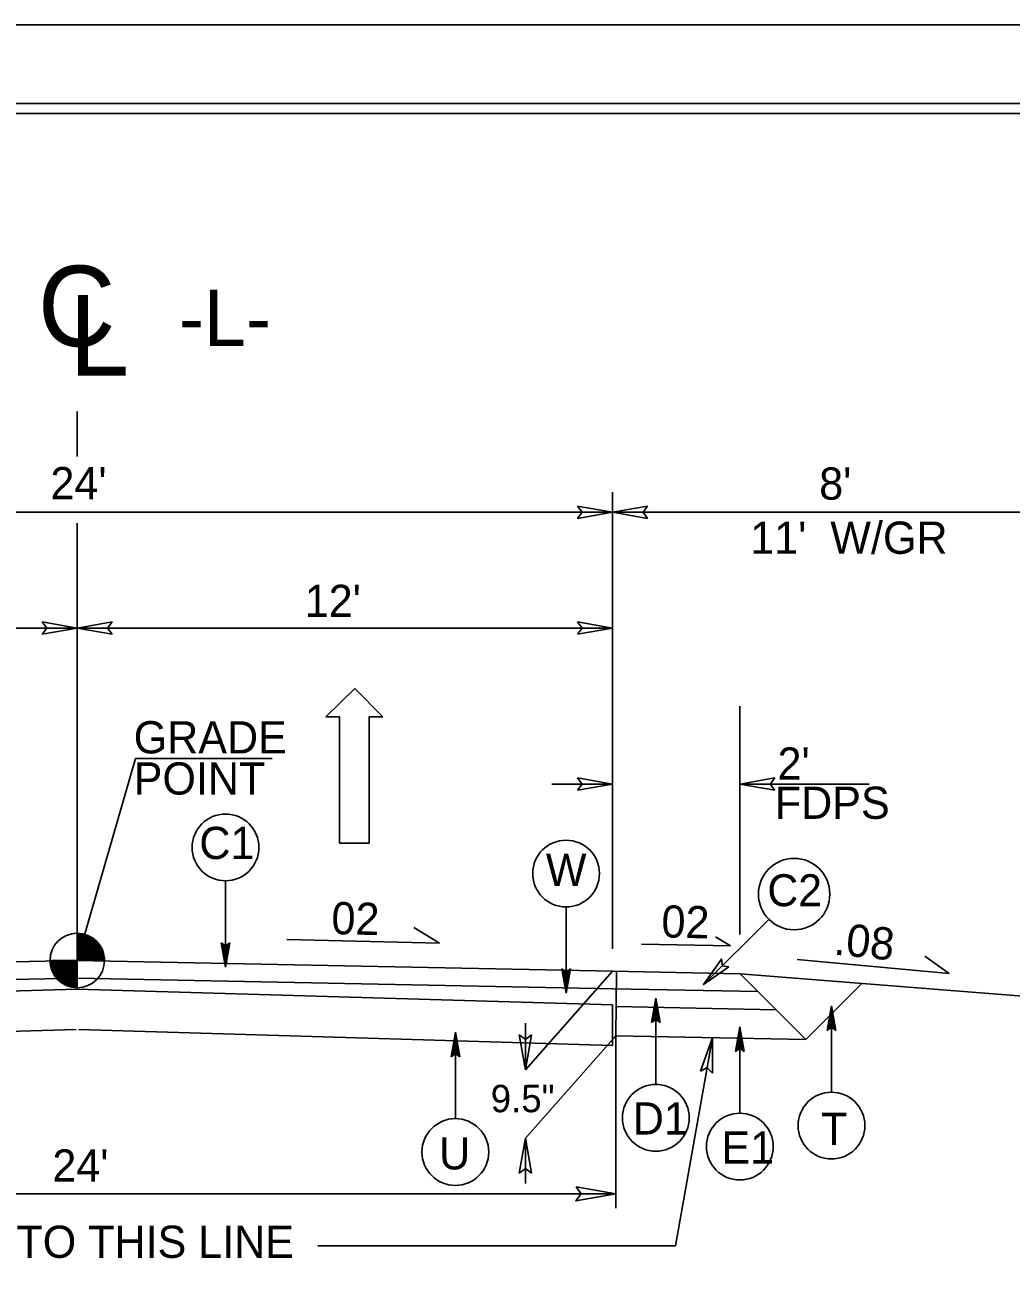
# Model space of a CAD drawing. Extents: x 2532463 to 2534146, y 189689 to 190784.
# Drawn here: x 2533450.3 to 2533701.3, y 190466.5 to 190784.2 of the extents above; entities that cross this region are included whole.
import ezdxf

# ---------------------------------------------------------------- set-up
doc = ezdxf.new("R2010")
doc.units = 0
for name, color, linetype in [('Old_Level_1', 7, 'Continuous'), ('Old_Level_11', 7, 'Continuous'), ('Old_Level_12', 7, 'Continuous'), ('Old_Level_18', 7, 'Continuous'), ('Old_Level_2', 7, 'Continuous'), ('Old_Level_3', 7, 'Continuous'), ('Old_Level_4', 7, 'Continuous'), ('Old_Level_50', 7, 'Continuous'), ('Old_Level_51', 7, 'Continuous'), ('Typical Bridge Rail CELL', 7, 'Continuous'), ('Typical Curb CELL', 7, 'Continuous'), ('Typical ID Circle CELL', 7, 'Continuous'), ('Typical Shoulder Slope Information CELL', 7, 'Continuous')]:
    doc.layers.add(name, color=color, linetype=linetype)

msp = doc.modelspace()

# ---------------------------------------------------------------- linework, layer by layer
at = {"layer": 'Old_Level_1'}
for p, q in [((2533463.59, 190552.98), (2533463.59, 190546.03)), ((2533463.59, 190546.03), (2533463.59, 190552.98)), ((2533501.34, 190544.33), (2533500.24, 190550.56)), ((2533501.34, 190549.75), (2533500.24, 190550.56)), ((2533501.34, 190544.33), (2533500.4, 190550.45)), ((2533500.55, 190550.33), (2533501.34, 190544.33)), ((2533501.34, 190544.33), (2533500.71, 190550.21)), ((2533501.34, 190544.33), (2533502.44, 190550.56)), ((2533502.44, 190550.56), (2533501.34, 190549.75)), ((2533502.28, 190550.45), (2533501.34, 190544.33)), ((2533501.34, 190544.33), (2533502.12, 190550.33)), ((2533501.97, 190550.21), (2533501.34, 190544.33)), ((2533500.87, 190550.1), (2533501.34, 190544.33)), ((2533501.34, 190544.33), (2533501.02, 190549.99)), ((2533501.18, 190549.87), (2533501.34, 190544.33)), ((2533501.34, 190544.33), (2533501.81, 190550.1)), ((2533501.66, 190549.99), (2533501.34, 190544.33)), ((2533501.34, 190544.33), (2533501.5, 190549.87)), ((2533501.34, 190549.75), (2533501.34, 190544.33)), ((2533463.59, 190546.03), (2533327.27, 190543.31)), ((2533456.64, 190546.03), (2533463.59, 190546.03)), ((2533463.59, 190546.03), (2533463.59, 190539.09)), ((2533470.53, 190546.03), (2533463.59, 190546.03)), ((2533463.59, 190546.03), (2533599.9, 190543.31)), ((2533588.05, 190537.67), (2533586.96, 190543.9)), ((2533588.05, 190543.09), (2533586.96, 190543.9)), ((2533588.05, 190537.67), (2533587.11, 190543.79)), ((2533588.05, 190537.67), (2533589.15, 190543.9)), ((2533589.15, 190543.9), (2533588.05, 190543.09)), ((2533589, 190543.79), (2533588.05, 190537.67)), ((2533463.59, 190541.52), (2533327.27, 190538.8)), ((2533463.59, 190541.52), (2533599.9, 190538.8)), ((2533587.27, 190543.67), (2533588.05, 190537.67)), ((2533588.05, 190537.67), (2533587.43, 190543.55)), ((2533587.58, 190543.44), (2533588.05, 190537.67)), ((2533588.05, 190537.67), (2533587.74, 190543.33)), ((2533587.9, 190543.21), (2533588.05, 190537.67)), ((2533588.05, 190537.67), (2533588.84, 190543.67)), ((2533588.68, 190543.55), (2533588.05, 190537.67)), ((2533588.05, 190537.67), (2533588.53, 190543.44)), ((2533588.37, 190543.33), (2533588.05, 190537.67)), ((2533588.05, 190537.67), (2533588.21, 190543.21)), ((2533588.05, 190543.09), (2533588.05, 190537.67)), ((2533599.9, 190543.31), (2533632.37, 190542.66)), ((2533600.85, 190543.29), (2533600.75, 190526.87)), ((2533632.37, 190542.66), (2533649.13, 190525.9)), ((2533632.37, 190542.66), (2533710.89, 190536.38)), ((2533463.67, 190538.69), (2533327.27, 190534.75)), ((2533463.51, 190538.69), (2533599.9, 190534.75)), ((2533599.9, 190538.83), (2533636.94, 190538.09)), ((2533663.4, 190540.18), (2533649.13, 190525.9)), ((2533599.9, 190534.75), (2533599.9, 190524.39)), ((2533600.75, 190534.3), (2533641.54, 190533.49)), ((2533610.9, 190536.44), (2533609.8, 190530.21)), ((2533609.96, 190530.32), (2533610.9, 190536.44)), ((2533610.9, 190536.44), (2533610.12, 190530.44)), ((2533610.28, 190530.56), (2533610.9, 190536.44)), ((2533610.9, 190536.44), (2533610.43, 190530.67)), ((2533610.59, 190530.78), (2533610.9, 190536.44)), ((2533610.9, 190536.44), (2533610.75, 190530.9)), ((2533610.9, 190536.44), (2533612, 190530.21)), ((2533610.9, 190531.02), (2533610.9, 190536.44)), ((2533611.06, 190530.9), (2533610.9, 190536.44)), ((2533610.9, 190536.44), (2533611.22, 190530.78)), ((2533611.37, 190530.67), (2533610.9, 190536.44)), ((2533610.9, 190536.44), (2533611.53, 190530.56)), ((2533611.69, 190530.44), (2533610.9, 190536.44)), ((2533610.9, 190536.44), (2533611.85, 190530.32)), ((2533655.64, 190534.47), (2533654.54, 190528.24)), ((2533654.7, 190528.36), (2533655.64, 190534.47)), ((2533655.64, 190534.47), (2533654.85, 190528.47)), ((2533655.01, 190528.59), (2533655.64, 190534.47)), ((2533655.64, 190534.47), (2533655.17, 190528.7)), ((2533655.32, 190528.81), (2533655.64, 190534.47)), ((2533655.64, 190534.47), (2533655.48, 190528.93)), ((2533655.64, 190534.47), (2533656.74, 190528.24)), ((2533655.64, 190529.05), (2533655.64, 190534.47)), ((2533655.8, 190528.93), (2533655.64, 190534.47)), ((2533655.64, 190534.47), (2533655.95, 190528.81)), ((2533656.11, 190528.7), (2533655.64, 190534.47)), ((2533655.64, 190534.47), (2533656.27, 190528.59)), ((2533656.42, 190528.47), (2533655.64, 190534.47)), ((2533655.64, 190534.47), (2533656.58, 190528.36)), ((2533463.28, 190528.44), (2533327.27, 190524.39)), ((2533463.9, 190528.44), (2533599.9, 190524.39)), ((2533609.8, 190530.21), (2533610.9, 190531.02)), ((2533610.9, 190531.02), (2533612, 190530.21)), ((2533632.29, 190529.13), (2533631.19, 190522.89)), ((2533631.34, 190523.01), (2533632.29, 190529.13)), ((2533632.29, 190529.13), (2533631.5, 190523.13)), ((2533631.66, 190523.24), (2533632.29, 190529.13)), ((2533632.29, 190529.13), (2533631.82, 190523.36)), ((2533631.97, 190523.47), (2533632.29, 190529.13)), ((2533632.29, 190529.13), (2533632.13, 190523.59)), ((2533632.29, 190529.13), (2533633.39, 190522.89)), ((2533632.29, 190523.7), (2533632.29, 190529.13)), ((2533632.44, 190523.59), (2533632.29, 190529.13)), ((2533632.29, 190529.13), (2533632.6, 190523.47)), ((2533632.76, 190523.36), (2533632.29, 190529.13)), ((2533632.29, 190529.13), (2533632.91, 190523.24)), ((2533633.07, 190523.13), (2533632.29, 190529.13)), ((2533632.29, 190529.13), (2533633.23, 190523.01)), ((2533654.54, 190528.24), (2533655.64, 190529.05)), ((2533655.64, 190529.05), (2533656.74, 190528.24)), ((2533559.86, 190527.74), (2533558.76, 190521.5)), ((2533558.92, 190521.62), (2533559.86, 190527.74)), ((2533559.86, 190527.74), (2533559.08, 190521.74)), ((2533559.24, 190521.85), (2533559.86, 190527.74)), ((2533559.86, 190527.74), (2533559.39, 190521.97)), ((2533559.55, 190522.08), (2533559.86, 190527.74)), ((2533559.86, 190527.74), (2533559.71, 190522.2)), ((2533559.86, 190527.74), (2533560.96, 190521.5)), ((2533559.86, 190522.31), (2533559.86, 190527.74)), ((2533560.02, 190522.2), (2533559.86, 190527.74)), ((2533559.86, 190527.74), (2533560.18, 190522.08)), ((2533560.33, 190521.97), (2533559.86, 190527.74)), ((2533559.86, 190527.74), (2533560.49, 190521.85)), ((2533560.65, 190521.74), (2533559.86, 190527.74)), ((2533559.86, 190527.74), (2533560.81, 190521.62)), ((2533600.75, 190526.87), (2533649.13, 190525.9)), ((2533558.76, 190521.5), (2533559.86, 190522.31)), ((2533559.86, 190522.31), (2533560.96, 190521.5)), ((2533631.19, 190522.89), (2533632.29, 190523.7)), ((2533632.29, 190523.7), (2533633.39, 190522.89))]:
    msp.add_line(p, q, dxfattribs=at)
for points in [[(2533463.69, 190546.03), (2533463.69, 190552.98), (2533463.69, 190552.98)], [(2533463.82, 190546.03), (2533463.82, 190552.97)], [(2533463.96, 190546.03), (2533463.96, 190552.96)], [(2533464.1, 190546.03), (2533464.1, 190552.96)], [(2533464.24, 190546.03), (2533464.24, 190552.95)], [(2533464.38, 190546.03), (2533464.38, 190552.93)], [(2533464.52, 190546.03), (2533464.52, 190552.92)], [(2533464.66, 190546.03), (2533464.66, 190552.89)], [(2533464.79, 190546.03), (2533464.8, 190552.87)], [(2533464.93, 190546.03), (2533464.94, 190552.85)], [(2533465.07, 190546.03), (2533465.07, 190552.82)], [(2533465.21, 190546.03), (2533465.21, 190552.78)], [(2533465.35, 190546.03), (2533465.35, 190552.75)], [(2533465.49, 190546.03), (2533465.49, 190552.71)], [(2533465.63, 190546.03), (2533465.63, 190552.67)], [(2533465.77, 190546.03), (2533465.77, 190552.63)], [(2533465.9, 190546.03), (2533465.9, 190552.58)], [(2533466.05, 190546.03), (2533466.05, 190552.53)], [(2533466.18, 190546.03), (2533466.19, 190552.47)], [(2533466.32, 190546.03), (2533466.32, 190552.42)], [(2533466.46, 190546.03), (2533466.47, 190552.35)], [(2533466.6, 190546.03), (2533466.6, 190552.29)], [(2533466.74, 190546.03), (2533466.74, 190552.22)], [(2533466.88, 190546.03), (2533466.88, 190552.15)], [(2533467.02, 190546.03), (2533467.02, 190552.07)], [(2533467.15, 190546.03), (2533467.16, 190551.99)], [(2533467.3, 190546.03), (2533467.3, 190551.9)], [(2533467.43, 190546.03), (2533467.44, 190551.81)], [(2533467.57, 190546.03), (2533467.57, 190551.72)], [(2533467.71, 190546.03), (2533467.71, 190551.62)], [(2533467.85, 190546.03), (2533467.85, 190551.51)], [(2533467.99, 190546.03), (2533467.99, 190551.4)], [(2533468.13, 190546.03), (2533468.13, 190551.28)], [(2533468.27, 190546.03), (2533468.27, 190551.16)], [(2533468.4, 190546.03), (2533468.41, 190551.03)], [(2533468.55, 190546.03), (2533468.55, 190550.89)], [(2533468.68, 190546.03), (2533468.68, 190550.75)], [(2533468.82, 190546.03), (2533468.82, 190550.59)], [(2533468.96, 190546.03), (2533468.96, 190550.43)], [(2533469.1, 190546.03), (2533469.1, 190550.25)], [(2533469.24, 190546.03), (2533469.24, 190550.07)], [(2533469.38, 190546.03), (2533469.38, 190549.86)], [(2533469.52, 190546.03), (2533469.52, 190549.64)], [(2533469.66, 190546.03), (2533469.65, 190549.41)], [(2533469.8, 190546.03), (2533469.8, 190549.15)], [(2533469.93, 190546.03), (2533469.93, 190548.85)], [(2533470.07, 190546.03), (2533470.07, 190548.51)], [(2533470.21, 190546.03), (2533470.21, 190548.11)], [(2533470.35, 190546.03), (2533470.35, 190547.61)], [(2533456.72, 190545.05), (2533456.72, 190546.03)], [(2533456.85, 190544.35), (2533456.85, 190546.04)], [(2533456.99, 190543.86), (2533456.99, 190546.04)], [(2533457.13, 190543.48), (2533457.13, 190546.03)], [(2533457.27, 190543.16), (2533457.27, 190546.04)], [(2533457.41, 190542.86), (2533457.41, 190546.04)], [(2533457.55, 190542.61), (2533457.55, 190546.03)], [(2533457.69, 190542.38), (2533457.69, 190546.04)], [(2533457.82, 190542.16), (2533457.82, 190546.04)], [(2533457.96, 190541.96), (2533457.97, 190546.03)], [(2533458.1, 190541.78), (2533458.1, 190546.04)], [(2533458.24, 190541.61), (2533458.24, 190546.04)], [(2533458.38, 190541.44), (2533458.38, 190546.03)], [(2533458.52, 190541.29), (2533458.52, 190546.04)], [(2533458.66, 190541.15), (2533458.66, 190546.04)], [(2533458.8, 190541.01), (2533458.8, 190546.03)], [(2533458.93, 190540.88), (2533458.94, 190546.04)], [(2533459.07, 190540.76), (2533459.07, 190546.03)], [(2533459.21, 190540.64), (2533459.22, 190546.03)], [(2533459.35, 190540.53), (2533459.35, 190546.03)], [(2533459.49, 190540.43), (2533459.49, 190546.03)], [(2533459.63, 190540.33), (2533459.63, 190546.03)], [(2533459.77, 190540.24), (2533459.77, 190546.03)], [(2533459.9, 190540.14), (2533459.91, 190546.03)], [(2533460.05, 190540.06), (2533460.05, 190546.03)], [(2533460.18, 190539.98), (2533460.19, 190546.03)], [(2533460.33, 190539.91), (2533460.33, 190546.03)], [(2533460.46, 190539.83), (2533460.46, 190546.03)], [(2533460.6, 190539.76), (2533460.6, 190546.03)], [(2533460.74, 190539.7), (2533460.74, 190546.03)], [(2533460.88, 190539.64), (2533460.88, 190546.03)], [(2533461.02, 190539.58), (2533461.02, 190546.03)], [(2533461.16, 190539.53), (2533461.16, 190546.03)], [(2533461.29, 190539.48), (2533461.3, 190546.03)], [(2533461.43, 190539.43), (2533461.43, 190546.03)], [(2533461.58, 190539.39), (2533461.58, 190546.03)], [(2533461.71, 190539.35), (2533461.71, 190546.03)], [(2533461.85, 190539.31), (2533461.85, 190546.03)], [(2533461.99, 190539.28), (2533461.99, 190546.03)], [(2533462.13, 190539.24), (2533462.13, 190546.03)], [(2533462.27, 190539.22), (2533462.27, 190546.03)], [(2533462.41, 190539.19), (2533462.41, 190546.03)], [(2533462.55, 190539.17), (2533462.55, 190546.03)], [(2533462.68, 190539.15), (2533462.68, 190546.03)], [(2533462.83, 190539.13), (2533462.83, 190546.03)], [(2533462.96, 190539.12), (2533462.96, 190546.03)], [(2533463.1, 190539.11), (2533463.1, 190546.03)], [(2533463.24, 190539.1), (2533463.24, 190546.03)], [(2533463.38, 190539.1), (2533463.38, 190546.03)], [(2533463.52, 190539.09), (2533463.52, 190539.09), (2533463.52, 190546.03)], [(2533470.49, 190546.03), (2533470.49, 190546.79)]]:
    msp.add_lwpolyline(points, dxfattribs=at)
msp.add_circle((2533463.59, 190546.03), 6.94, dxfattribs=at)
for start, end in [(359.9906, 89.9906), (179.9906, 269.9906)]:
    msp.add_arc((2533463.59, 190546.03), 6.94, start, end, dxfattribs=at)
at = {"layer": 'Old_Level_11'}
msp.add_lwpolyline([(2533590.63, 190488.37), (2533600.75, 190486.63), (2533590.57, 190484.83), (2533591.87, 190486.63)], close=True, dxfattribs=at)
at = {"layer": 'Old_Level_18'}
msp.add_lwpolyline([(2534129.31, 190761.68), (2532629.31, 190761.68), (2532629.31, 189711.68), (2534129.31, 189711.68)], close=True, dxfattribs=at)
at = {"layer": 'Old_Level_2'}
for p, q in [((2533463.59, 190685.78), (2533463.59, 190674.32)), ((2533599.9, 190549), (2533599.9, 190665.28)), ((2533463.59, 190660.13), (2533327.27, 190660.13)), ((2533463.59, 190660.13), (2533599.9, 190660.13)), ((2533599.9, 190660.13), (2533710.84, 190660.13)), ((2533463.59, 190657.32), (2533463.59, 190542)), ((2533463.59, 190630.63), (2533327.27, 190630.63)), ((2533463.59, 190630.63), (2533599.9, 190630.63)), ((2533632.3, 190552.63), (2533632.3, 190610.73)), ((2533478.44, 190597.45), (2533463.59, 190546.03)), ((2533478.44, 190597.45), (2533513.23, 190597.45)), ((2533599.9, 190590.93), (2533584.41, 190590.93)), ((2533665.2, 190590.93), (2533632.3, 190590.93)), ((2533501.34, 190566.31), (2533501.34, 190544.33)), ((2533588.05, 190559.64), (2533588.05, 190537.67)), ((2533555.82, 190550.45), (2533549.3, 190554.42)), ((2533555.82, 190550.45), (2533516.96, 190551.36)), ((2533685.6, 190542.69), (2533679.38, 190547.1)), ((2533685.6, 190542.69), (2533646.9, 190546.29)), ((2533599.9, 190543.31), (2533577.69, 190518.18)), ((2533610.9, 190514.47), (2533610.9, 190536.44)), ((2533655.64, 190512.5), (2533655.64, 190534.47)), ((2533577.69, 190518.25), (2533577.69, 190530.08)), ((2533632.29, 190507.15), (2533632.29, 190529.13)), ((2533559.86, 190505.76), (2533559.86, 190527.74)), ((2533600.75, 190526.87), (2533577.69, 190500.78)), ((2533600.75, 190526.87), (2533600.75, 190482.99)), ((2533625.36, 190526.38), (2533615.91, 190473.41)), ((2533577.69, 190489.21), (2533577.69, 190500.78)), ((2533463.59, 190486.63), (2533326.42, 190486.63)), ((2533463.59, 190486.63), (2533600.75, 190486.63)), ((2533615.91, 190473.41), (2533524.83, 190473.41))]:
    msp.add_line(p, q, dxfattribs=at)
for centre in [(2533501.34, 190574.81), (2533588.05, 190568.15), (2533610.9, 190505.96), (2533655.64, 190503.99), (2533559.86, 190497.26), (2533632.29, 190498.65)]:
    msp.add_circle(centre, 8.5, dxfattribs=at)
at = {"layer": 'Old_Level_3'}
for p, q in [((2533599.9, 190660.13), (2533591, 190661.7)), ((2533591, 190661.7), (2533592.16, 190660.13)), ((2533599.9, 190660.13), (2533608.81, 190661.7)), ((2533608.81, 190661.7), (2533607.65, 190660.13)), ((2533591, 190658.56), (2533599.9, 190660.13)), ((2533592.16, 190660.13), (2533591, 190658.56)), ((2533608.81, 190658.56), (2533599.9, 190660.13)), ((2533607.65, 190660.13), (2533608.81, 190658.56)), ((2533463.59, 190630.63), (2533454.68, 190632.2)), ((2533454.68, 190632.2), (2533455.84, 190630.63)), ((2533454.68, 190629.06), (2533463.59, 190630.63)), ((2533455.84, 190630.63), (2533454.68, 190629.06)), ((2533463.59, 190630.63), (2533472.49, 190632.2)), ((2533472.49, 190629.06), (2533463.59, 190630.63)), ((2533472.49, 190632.2), (2533471.33, 190630.63)), ((2533471.33, 190630.63), (2533472.49, 190629.06)), ((2533599.9, 190630.63), (2533591, 190632.2)), ((2533591, 190632.2), (2533592.16, 190630.63)), ((2533591, 190629.06), (2533599.9, 190630.63)), ((2533592.16, 190630.63), (2533591, 190629.06)), ((2533599.9, 190590.93), (2533591, 190592.5)), ((2533591, 190592.5), (2533592.16, 190590.93)), ((2533632.3, 190590.93), (2533641.21, 190592.5)), ((2533641.21, 190592.5), (2533640.05, 190590.93)), ((2533591, 190589.36), (2533599.9, 190590.93)), ((2533592.16, 190590.93), (2533591, 190589.36)), ((2533641.21, 190589.36), (2533632.3, 190590.93)), ((2533640.05, 190590.93), (2533641.21, 190589.36)), ((2533577.69, 190518.18), (2533576.12, 190527.08)), ((2533576.12, 190527.08), (2533577.69, 190525.92)), ((2533579.26, 190527.08), (2533577.69, 190518.18)), ((2533577.69, 190525.92), (2533579.26, 190527.08)), ((2533625.36, 190526.38), (2533622.25, 190517.89)), ((2533625.34, 190517.34), (2533625.36, 190526.38)), ((2533622.25, 190517.89), (2533624, 190518.76)), ((2533624, 190518.76), (2533625.34, 190517.34)), ((2533576.12, 190491.87), (2533577.69, 190500.78)), ((2533577.69, 190500.78), (2533579.26, 190491.87)), ((2533577.69, 190493.03), (2533576.12, 190491.87)), ((2533579.26, 190491.87), (2533577.69, 190493.03))]:
    msp.add_line(p, q, dxfattribs=at)
at = {"layer": 'Old_Level_4'}
for p, q in [((2533534.26, 190615.27), (2533526.92, 190608.04)), ((2533541.38, 190608.05), (2533534.26, 190615.27)), ((2533526.92, 190608.04), (2533530.36, 190608.04)), ((2533530.36, 190608.04), (2533530.37, 190575.91)), ((2533537.95, 190575.92), (2533537.94, 190608.05)), ((2533537.94, 190608.05), (2533541.38, 190608.05)), ((2533530.37, 190575.91), (2533537.95, 190575.92))]:
    msp.add_line(p, q, dxfattribs=at)
at = {"layer": 'Old_Level_50'}
msp.add_lwpolyline([(2532475.81, 189709.18), (2534141.81, 189709.18), (2534141.81, 190764.18), (2532475.81, 190764.18)], close=True, dxfattribs=at)
at = {"layer": 'Old_Level_51'}
msp.add_lwpolyline([(2532462.81, 189689.18), (2534146.31, 189689.18), (2534146.31, 190784.18), (2532462.81, 190784.18)], close=True, dxfattribs=at)
at = {"layer": 'Typical Bridge Rail CELL'}
msp.add_line((2533639.7, 190556.5), (2533623.08, 190539.89), dxfattribs=at)
msp.add_circle((2533646.12, 190562.93), 9.09, dxfattribs=at)
at = {"layer": 'Typical Curb CELL'}
for q in [(2533607.25, 190550.2), (2533626.09, 190552.05)]:
    msp.add_line((2533629.89, 190549.75), q, dxfattribs=at)
at = {"layer": 'Typical ID Circle CELL'}
msp.add_lwpolyline([(2533629.51, 190544.43), (2533623.08, 190539.89), (2533627.62, 190546.38), (2533627.89, 190544.7)], close=True, dxfattribs=at)

# ---------------------------------------------------------------- texts
at = {"layer": 'Old_Level_12'}
for s, height, rotation, p in [("24'", 8.201, 0.0001, (2533456.77, 190663.45)), ("12'", 8.201, 0.0001, (2533521.52, 190633.47)), ('C1', 8.201, 0.0001, (2533494.68, 190571.85)), ('W', 8.2, 0.0001, (2533582.9, 190565.02)), ('D1', 8.201, 359.9999, (2533605.04, 190501.72)), ('T', 8.2, 0.0001, (2533652.96, 190499.08)), ('E1', 8.201, 359.9999, (2533627.61, 190494.31)), ('U', 8.2, 0.0001, (2533555.72, 190492.84)), ("24'", 8.201, 0.0001, (2533457.25, 190489.74)), ('GRADE TO THIS LINE', 8.2009, 0.0001, (2533406.05, 190470.32))]:
    msp.add_text(s, height=height, rotation=rotation, dxfattribs=at).set_placement(p)
at = {"layer": 'Old_Level_2'}
for s, height, rotation, p in [("8'", 8.201, 0.0001, (2533652.5, 190663.34)), ("11'  W/GR", 8.201, 0.0001, (2533634.95, 190649.55)), ('GRADE ', 8.201, 0.0001, (2533477.96, 190598.74)), ("2'", 8.201, 0.0001, (2533641.9, 190592.07)), ('POINT', 8.201, 0.0001, (2533477.96, 190588.26)), ('FDPS', 8.201, 0.0001, (2533641.21, 190582.08)), ('.08', 8.201, 354.1668, (2533656.04, 190547.56)), ('9.5"', 6.971, 0.0462, (2533568.87, 190507.39))]:
    msp.add_text(s, height=height, rotation=rotation, dxfattribs=at).set_placement(p)
at = {"layer": 'Old_Level_3'}
for s, height, rotation, p in [('C', 20.5, 0.0001, (2533453.54, 190702.39)), ('L', 20.5, 0.0001, (2533461.54, 190694.92)), ('-L-', 14.352, 0.0001, (2533489.46, 190702.47)), ('02', 8.201, 358.6184, (2533528.24, 190552.76)), ('02', 8.201, 358.6184, (2533612.27, 190551.91))]:
    msp.add_text(s, height=height, rotation=rotation, dxfattribs=at).set_placement(p)
at = {"layer": 'Typical Shoulder Slope Information CELL'}
msp.add_text('C2', height=8.135, dxfattribs=at).set_placement((2533639.31, 190559.84))

doc.saveas('drawing.dxf')
